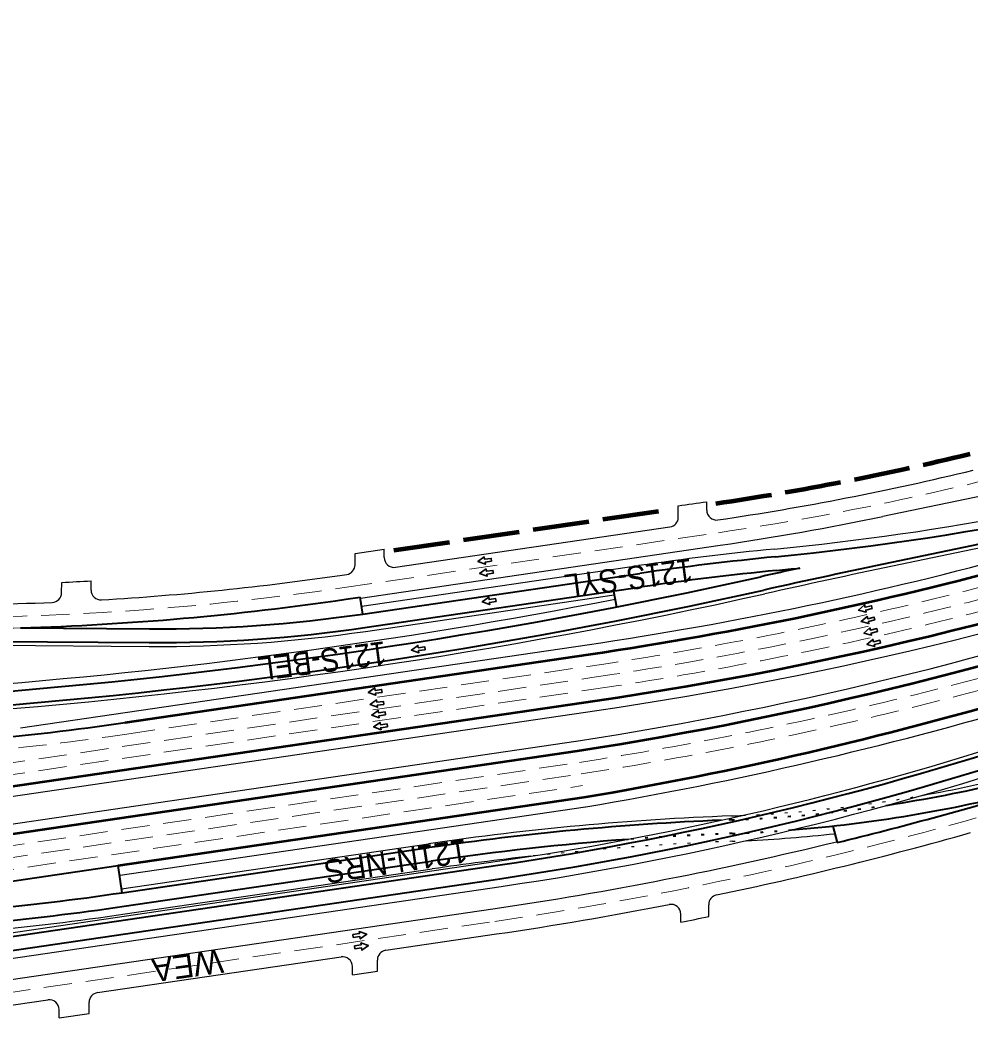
# Model space of a CAD drawing. Extents: x 2329387 to 2347382, y 6951580 to 6987999.
# Drawn here: x 2335420 to 2336392, y 6964774 to 6965820 of the extents above; entities that cross this region are included whole.
import ezdxf

# ---------------------------------------------------------------- set-up
doc = ezdxf.new("R2010")
doc.units = 0
doc.header["$LTSCALE"] = 9.6
for name, pattern in [('DOTTED', [1.5, 0.3, -1.2]), ('LONG_DASHED', [7.5, 6, -1.5]), ('MEDIUM_DASHED', [4.5, 3, -1.5])]:
    doc.linetypes.add(name, pattern=pattern)
for name, color, linetype, lineweight in [('26', 7, 'Continuous', 53), ('27', 7, 'Continuous', 40), ('28', 7, 'Continuous', 25), ('41', 7, 'Continuous', 35), ('50', 7, 'MEDIUM_DASHED', 13), ('59', 7, 'LONG_DASHED', 90)]:
    doc.layers.add(name, color=color, linetype=linetype, lineweight=lineweight)
doc.layers.add('40', color=7, linetype='Continuous')

msp = doc.modelspace()

# ---------------------------------------------------------------- linework, layer by layer
at = {"layer": '26', "lineweight": 25}
for p, q in [((2335419.78, 6965095.693), (2335999.546, 6965180.848)), ((2334914.266, 6964952.715), (2336009.413, 6965113.568)), ((2334913.997, 6964924.375), (2335988.149, 6965082.144)), ((2335521.841, 6964944.924), (2335998.03, 6965014.866))]:
    msp.add_line(p, q, dxfattribs=at)
at = {"layer": '26'}
for p, q in [((2335526.978, 6965101.331), (2336000.988, 6965170.952)), ((2334914.362, 6964962.836), (2336007.96, 6965123.461)), ((2334913.901, 6964914.254), (2335989.602, 6965072.25)), ((2335519.679, 6964954.714), (2335996.577, 6965024.759))]:
    msp.add_line(p, q, dxfattribs=at)
for centre, radius, start, end in [((2335453.211, 6968900.408), 3817.469, 278.35573, 300.65952), ((2335400.739, 6968870.593), 3843.719, 278.81536, 299.60537), ((2335348.901, 6968850.035), 3879.719, 279.60989, 293.40387), ((2335453.211, 6968900.408), 3769.469, 278.35579, 285.32717)]:
    msp.add_arc(centre, radius, start, end, dxfattribs=at)
at = {"layer": '26', "lineweight": 25}
for centre, radius, start, end in [((2335453.211, 6968900.408), 3827.469, 278.35573, 300.65952), ((2335400.739, 6968870.593), 3833.719, 278.81536, 299.60537), ((2335348.901, 6968850.035), 3889.719, 279.60989, 293.40175), ((2335453.211, 6968900.408), 3759.469, 278.35579, 285.32717)]:
    msp.add_arc(centre, radius, start, end, dxfattribs=at)
at = {"layer": '27', "lineweight": 25}
for p, q in [((2335768.913, 6965220.251), (2336052.272, 6965261.87)), ((2335772.691, 6965194.527), (2336027.239, 6965231.914)), ((2335312.188, 6965180.869), (2335551.616, 6965179.167)), ((2335523.166, 6964930.968), (2335837.264, 6964977.103)), ((2334912.942, 6964813.04), (2335907.743, 6964959.154)), ((2335526.945, 6964905.244), (2335841.043, 6964951.379)), ((2334912.692, 6964786.724), (2335911.521, 6964933.43))]:
    msp.add_line(p, q, dxfattribs=at)
at = {"layer": '27'}
for p, q in [((2335770.075, 6965212.336), (2336053.43, 6965253.954)), ((2335772.11, 6965198.484), (2336055.464, 6965240.103)), ((2335752.615, 6965227.459), (2335767.532, 6965229.65)), ((2335770.075, 6965212.336), (2335767.532, 6965229.65)), ((2336026.472, 6965235.844), (2336029.635, 6965219.651)), ((2335419.789, 6965198.105), (2335551.744, 6965197.167)), ((2335312.216, 6965184.869), (2335551.644, 6965183.167)), ((2336251.088, 6964995.285), (2336255.253, 6964978.287)), ((2335523.748, 6964927.011), (2335837.846, 6964973.145)), ((2335525.782, 6964913.16), (2335839.88, 6964959.294)), ((2334912.903, 6964808.991), (2335908.324, 6964955.196)), ((2335046.491, 6964885.213), (2335519.679, 6964954.714)), ((2335523.748, 6964927.011), (2335519.679, 6964954.714)), ((2334912.769, 6964794.821), (2335910.358, 6964941.345))]:
    msp.add_line(p, q, dxfattribs=at)
for centre, radius, start, end in [((2339406.145, 6959556.474), 7976, 170.51466, 170.51466), ((2335914.539, 6968122.19), 2864.789, 275.56071, 300.68463), ((2335434.579, 6968180.635), 3260.044, 278.35573, 300.00238), ((2335434.579, 6968180.635), 3274.044, 278.35573, 300.00238), ((2338670.145, 6954065.803), 11445.156, 101.22505, 102.56422), ((2336469.737, 6962419.575), 2864.789, 95.56071, 98.35573), ((2334931.002, 6970842.912), 5729.578, 274.27965, 282.56422), ((2336469.737, 6962419.575), 2850.789, 95.56071, 98.35573), ((2338670.145, 6954065.803), 11459.156, 102.35975, 102.56422), ((2335914.539, 6968122.19), 2878.789, 275.56071, 276.0374), ((2334931.016, 6970842.915), 5743.578, 274.27952, 282.56422), ((2335332.828, 6968085.584), 2888.789, 271.72504, 278.35557), ((2335561.922, 6966629.525), 1432.395, 269.59288, 278.35573), ((2335561.922, 6966629.525), 1446.395, 269.59288, 278.35573), ((2335110.67, 6967935.71), 2864.789, 275.26524, 278.35573), ((2336093.959, 6966419.035), 1418.394, 278.65967, 288.28285), ((2336093.959, 6966419.035), 1432.394, 274.60744, 284.44642), ((2335351.623, 6968665.906), 3796.719, 283.76869, 286.8364), ((2336256.187, 6962124.915), 2878.789, 92.37551, 98.35573), ((2336256.187, 6962124.915), 2864.789, 94.29905, 98.35573), ((2335109.475, 6967747.539), 2850.789, 272.48994, 278.35573), ((2335109.475, 6967747.539), 2864.789, 272.48994, 278.35573)]:
    msp.add_arc(centre, radius, start, end, dxfattribs=at)
at = {"layer": '27', "lineweight": 25}
for centre, radius, start, end in [((2335914.539, 6968122.19), 2856.789, 275.56071, 296.28739), ((2335434.579, 6968180.635), 3282.044, 278.35573, 300.00238), ((2338670.145, 6954065.803), 11441.156, 101.22361, 102.56422), ((2335434.579, 6968180.635), 3256.044, 278.35573, 296.69097), ((2336469.737, 6962419.575), 2872.789, 95.56071, 98.35563), ((2334931.016, 6970842.915), 5747.578, 274.27952, 282.56422), ((2334931.002, 6970842.912), 5721.578, 274.27965, 281.05479), ((2335561.922, 6966629.525), 1450.395, 269.59288, 278.35573), ((2336093.959, 6966419.035), 1414.394, 280.11263, 288.28285), ((2336256.187, 6962124.915), 2882.789, 92.16356, 98.35573), ((2336093.959, 6966419.035), 1414.394, 272.16356, 272.6216), ((2336093.959, 6966419.035), 1440.394, 272.71439, 276.33955), ((2336256.187, 6962124.915), 2856.789, 96.31318, 98.35573), ((2335109.475, 6967747.539), 2872.789, 272.48994, 278.35573)]:
    msp.add_arc(centre, radius, start, end, dxfattribs=at)
at = {"layer": '27', "linetype": 'DOTTED', "lineweight": 25}
for centre, radius, start, end in [((2336093.959, 6966419.035), 1414.394, 272.62161, 280.11263), ((2336256.187, 6962124.915), 2856.789, 92.16356, 96.31318), ((2336093.959, 6966419.035), 1440.394, 272.16356, 272.71439)]:
    msp.add_arc(centre, radius, start, end, dxfattribs=at)
at = {"layer": '27', "linetype": 'DOTTED'}
for centre, radius, start, end in [((2336093.959, 6966419.035), 1418.394, 272.16356, 278.65967), ((2336256.187, 6962124.915), 2878.789, 92.16356, 92.37551), ((2336093.959, 6966419.035), 1432.394, 272.16356, 274.60744), ((2336256.187, 6962124.915), 2864.789, 92.16356, 94.29905)]:
    msp.add_arc(centre, radius, start, end, dxfattribs=at)
at = {"layer": '28'}
for p, q in [((2336560.342, 6965365.66), (2336302.2, 6965312.166)), ((2336092.866, 6965311.403), (2336092.794, 6965323.145)), ((2336121.979, 6965318.584), (2336122.004, 6965327.206)), ((2335803.416, 6965260.189), (2336084.32, 6965301.447)), ((2335767.678, 6965228.661), (2336135.756, 6965282.723)), ((2335762.135, 6965262.665), (2335762.251, 6965274.357)), ((2335762.251, 6965274.357), (2335792.029, 6965278.731)), ((2335791.963, 6965270.159), (2335792.029, 6965278.731)), ((2335461.911, 6965234.193), (2335462.003, 6965244.731)), ((2335492, 6965236.844), (2335492.028, 6965246.255)), ((2336124.223, 6964902.677), (2336124.023, 6964914.751)), ((2334924.049, 6964766.661), (2335903.212, 6964910.479)), ((2336095.448, 6964896.883), (2336095.438, 6964905.122)), ((2335793.487, 6964868.084), (2335906.973, 6964884.752)), ((2335498.558, 6964824.765), (2335747.907, 6964861.389)), ((2335785.098, 6964846.637), (2335784.941, 6964858.052)), ((2335759.375, 6964842.859), (2335759.36, 6964851.512)), ((2335759.375, 6964842.859), (2335785.098, 6964846.637)), ((2335199.022, 6964780.77), (2335447.877, 6964817.321)), ((2335489.949, 6964803.286), (2335490.011, 6964814.925)), ((2335459.312, 6964798.786), (2335459.33, 6964807.407)), ((2335459.312, 6964798.786), (2335489.949, 6964803.286))]:
    msp.add_line(p, q, dxfattribs=at)
for centre, radius, start, end in [((2335715.816, 6968141.837), 2863.789, 278.38524, 283.71181), ((2335715.816, 6968141.837), 2843.789, 277.61765, 278.21184), ((2336131.979, 6965318.555), 10, 179.8324, 278.38524), ((2335715.816, 6968141.837), 2889.789, 278.35573, 281.70752), ((2336082.867, 6965311.341), 10, 278.35573, 0.35516), ((2335752.135, 6965262.764), 10, 278.35573, 359.43075), ((2335801.963, 6965270.083), 10, 179.5623, 278.35573), ((2335332.828, 6968085.584), 2863.789, 273.39848, 278.35557), ((2335332.828, 6968085.584), 2843.789, 272.60348, 273.20919), ((2335451.911, 6965234.281), 10, 272.39154, 359.49836), ((2335502, 6965236.814), 10, 179.82998, 273.39847), ((2335332.828, 6968085.584), 2863.789, 269.57532, 272.39154), ((2335351.623, 6968665.906), 3821.719, 281.78209, 285.79501), ((2335351.623, 6968665.906), 3795.719, 278.35573, 283.76869), ((2335351.623, 6968665.906), 3821.719, 278.35547, 281.04095), ((2336085.438, 6964905.11), 10, 0.0684, 101.04095), ((2336134.022, 6964914.916), 10, 101.78209, 180.94795), ((2335351.623, 6968665.906), 3841.719, 281.16397, 281.60175), ((2335794.94, 6964858.19), 10, 98.35573, 180.78921), ((2335749.36, 6964851.495), 10, 0.0978, 98.35573), ((2335500.011, 6964814.871), 10, 98.35573, 179.69327), ((2335449.33, 6964807.427), 10, 359.88421, 98.35573)]:
    msp.add_arc(centre, radius, start, end, dxfattribs=at)
at = {"layer": '41'}
for points in [[(2335901.856, 6965266.342), (2335901.42, 6965269.311), (2335894.686, 6965268.321), (2335894.331, 6965270.732), (2335887.757, 6965265.946), (2335895.43, 6965263.255), (2335895.122, 6965265.352)], [(2335903.707, 6965254.056), (2335903.271, 6965257.024), (2335896.537, 6965256.034), (2335896.182, 6965258.446), (2335889.608, 6965253.66), (2335897.281, 6965250.968), (2335896.973, 6965253.065)], [(2335906.39, 6965225.122), (2335905.954, 6965228.091), (2335899.219, 6965227.101), (2335898.865, 6965229.512), (2335892.291, 6965224.726), (2335899.964, 6965222.035), (2335899.656, 6965224.132)], [(2336291.302, 6965217.919), (2336290.602, 6965220.837), (2336283.983, 6965219.251), (2336283.415, 6965221.621), (2336277.294, 6965216.268), (2336285.177, 6965214.271), (2336284.683, 6965216.333)], [(2336293.966, 6965206.219), (2336293.267, 6965209.137), (2336286.648, 6965207.55), (2336286.08, 6965209.92), (2336279.959, 6965204.567), (2336287.841, 6965202.571), (2336287.347, 6965204.632)], [(2336296.803, 6965194.471), (2336296.103, 6965197.389), (2336289.484, 6965195.802), (2336288.916, 6965198.172), (2336282.795, 6965192.819), (2336290.678, 6965190.823), (2336290.184, 6965192.884)], [(2335833.915, 6965175.812), (2335833.479, 6965178.781), (2335826.745, 6965177.791), (2335826.39, 6965180.202), (2335819.816, 6965175.416), (2335827.489, 6965172.725), (2335827.181, 6965174.822)], [(2336299.913, 6965182.635), (2336299.213, 6965185.553), (2336292.594, 6965183.967), (2336292.026, 6965186.337), (2336285.905, 6965180.984), (2336293.787, 6965178.988), (2336293.293, 6965181.049)], [(2335789.703, 6965132.092), (2335789.315, 6965135.068), (2335782.566, 6965134.187), (2335782.25, 6965136.604), (2335775.599, 6965131.926), (2335783.228, 6965129.11), (2335782.954, 6965131.212)], [(2335791.619, 6965119.848), (2335791.231, 6965122.823), (2335784.481, 6965121.943), (2335784.166, 6965124.359), (2335777.515, 6965119.681), (2335785.144, 6965116.865), (2335784.87, 6965118.967)], [(2335793.341, 6965109.091), (2335792.953, 6965112.066), (2335786.203, 6965111.186), (2335785.888, 6965113.602), (2335779.237, 6965108.924), (2335786.865, 6965106.108), (2335786.591, 6965108.21)], [(2335795.257, 6965096.846), (2335794.868, 6965099.821), (2335788.119, 6965098.941), (2335787.804, 6965101.358), (2335781.153, 6965096.679), (2335788.781, 6965093.863), (2335788.507, 6965095.965)], [(2335759.915, 6964884.239), (2335760.304, 6964881.263), (2335767.053, 6964882.144), (2335767.368, 6964879.727), (2335774.019, 6964884.406), (2335766.391, 6964887.221), (2335766.665, 6964885.12)], [(2335761.617, 6964872.651), (2335762.006, 6964869.676), (2335768.755, 6964870.556), (2335769.07, 6964868.139), (2335775.721, 6964872.818), (2335768.093, 6964875.633), (2335768.367, 6964873.532)]]:
    msp.add_lwpolyline(points, close=True, dxfattribs=at)
at = {"layer": '50'}
for p, q in [((2335750.873, 6965239.332), (2336133.867, 6965295.585)), ((2335528.721, 6965089.458), (2336002.728, 6965159.079)), ((2334925.608, 6964988.745), (2336004.472, 6965147.207)), ((2334925.493, 6964976.6), (2336006.216, 6965135.334)), ((2334924.802, 6964903.726), (2335991.346, 6965060.377)), ((2334928.405, 6964892.126), (2335993.089, 6965048.505)), ((2335213.626, 6964921.89), (2335994.833, 6965036.632)), ((2334930.91, 6964754.53), (2335905.116, 6964897.619))]:
    msp.add_line(p, q, dxfattribs=at)
at = {"layer": '50', "linetype": 'Continuous', "lineweight": 25}
msp.add_line((2335748.99, 6965252.195), (2335753.589, 6965252.87), dxfattribs=at)
at = {"layer": '50'}
for centre, radius, start, end in [((2335453.211, 6968900.408), 3781.469, 278.35579, 300.65952), ((2335453.211, 6968900.408), 3793.469, 278.35573, 300.65952), ((2335453.211, 6968900.408), 3805.469, 278.35573, 300.65952), ((2335400.739, 6968870.593), 3855.719, 278.81536, 299.60537), ((2335400.739, 6968870.593), 3867.719, 278.81536, 299.60537), ((2335715.816, 6968141.837), 2876.789, 278.35573, 293.37001), ((2335332.828, 6968085.584), 2876.789, 269.57533, 278.35561), ((2335332.828, 6968085.584), 2888.789, 269.57526, 271.72504), ((2335351.623, 6968665.906), 3808.719, 278.35596, 293.24673), ((2335110.67, 6967935.71), 2876.789, 275.26524, 278.35573)]:
    msp.add_arc(centre, radius, start, end, dxfattribs=at)
at = {"layer": '59'}
msp.add_line((2335801.844, 6965277.597), (2336081.659, 6965319.088), dxfattribs=at)
msp.add_arc((2335715.816, 6968141.837), 2846.789, 278.3908, 283.72902, dxfattribs=at)

# ---------------------------------------------------------------- texts
at = {"layer": '40'}
for s, rotation, width, p in [('121S-SYL', 187.381, 0.9, (2336105.806, 6965269.281)), ('121S-BEL', 187.381, 0.9, (2335792.355, 6965184.573)), ('121N-NRS', 188.63, 0.95, (2335875.125, 6964982.158))]:
    msp.add_text(s, height=24, rotation=rotation, dxfattribs=dict(at, width=width)).set_placement(p)
msp.add_text('WEA', height=24, rotation=187.853, dxfattribs=at).set_placement((2335625.367, 6964869.033))

doc.saveas('drawing.dxf')
